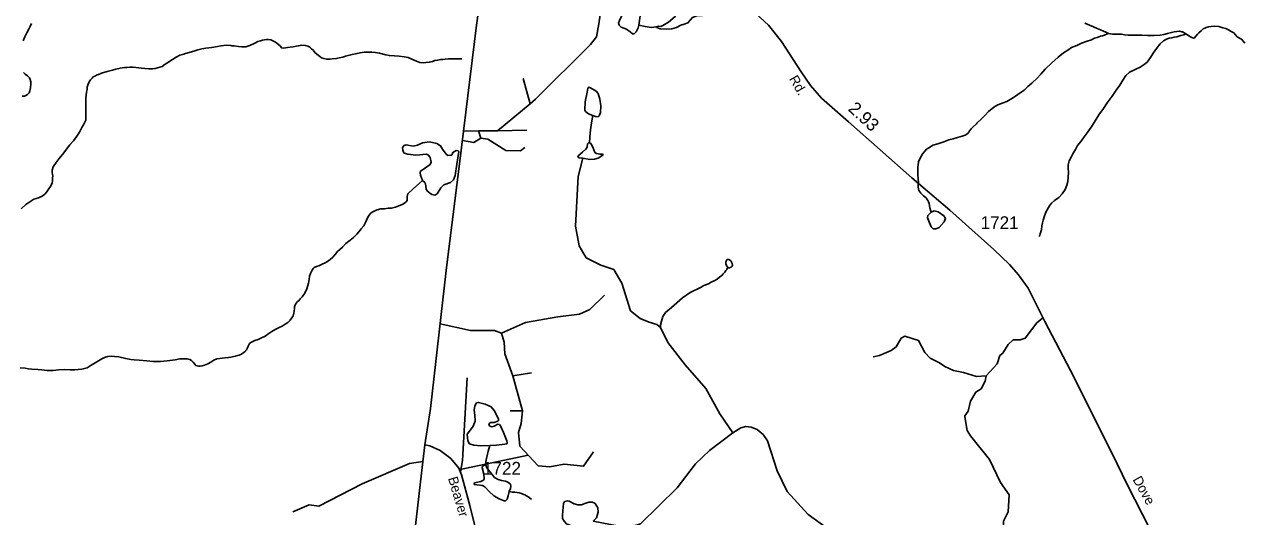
# Model space of a CAD drawing. Extents: x 2056842 to 2160602, y 826753 to 1016856.
# Drawn here: x 2087342 to 2099244, y 851032 to 855845 of the extents above; entities that cross this region are included whole.
import ezdxf

# ---------------------------------------------------------------- set-up
doc = ezdxf.new("R2010")
doc.units = 0
for name, color, linetype in [('Exist Hydrographic Creek Single Shore', 7, 'Continuous'), ('Exist Hydrographic Misc Water Feature', 7, 'Continuous'), ('Exist Road Non-System Type 51', 7, 'Continuous'), ('Exist Road Primary NC Attributed', 7, 'Continuous'), ('Exist Road Secondary Mileage Hundredths English Label', 7, 'Continuous'), ('Exist Road Secondary Type 51 Attributed', 7, 'Continuous'), ('Exist Road Secondary Type 51 Label', 7, 'Continuous'), ('Exist Road Secondary Type 51 Number Label', 7, 'Continuous')]:
    doc.layers.add(name, color=color, linetype=linetype)

msp = doc.modelspace()

# ---------------------------------------------------------------- linework, layer by layer
at = {"layer": 'Exist Hydrographic Creek Single Shore'}
for points in [[(2087412, 855852), (2087397, 855824), (2087386, 855797), (2087366, 855761), (2087346, 855722), (2087330, 855685)], [(2097702, 855856), (2097748, 855836), (2097788, 855820), (2097824, 855804), (2097854, 855792), (2097884, 855778), (2097906, 855768), (2097934, 855756)], [(2097934, 855756), (2097954, 855751), (2097973, 855749), (2097994, 855749), (2098026, 855749), (2098062, 855747), (2098091, 855741), (2098127, 855739), (2098164, 855739), (2098215, 855739), (2098260, 855739), (2098314, 855737), (2098380, 855736), (2098439, 855740), (2098474, 855746), (2098510, 855754), (2098548, 855764), (2098576, 855772), (2098600, 855776), (2098626, 855779), (2098650, 855773), (2098658, 855770), (2098680, 855759), (2098688, 855753)], [(2098688, 855753), (2098704, 855741), (2098728, 855727), (2098748, 855715), (2098764, 855709), (2098770, 855711), (2098790, 855731), (2098802, 855747), (2098816, 855761), (2098842, 855785), (2098858, 855801), (2098874, 855807), (2098888, 855813), (2098912, 855819), (2098936, 855823), (2098972, 855826), (2099012, 855822), (2099052, 855812), (2099080, 855804), (2099106, 855792), (2099132, 855776), (2099158, 855760), (2099176, 855742), (2099192, 855724), (2099214, 855710), (2099233, 855700), (2099266, 855660)], [(2091616, 855507), (2091540, 855509), (2091484, 855506), (2091452, 855504), (2091430, 855502), (2091406, 855500), (2091380, 855496), (2091352, 855490), (2091330, 855482), (2091298, 855474), (2091264, 855470), (2091246, 855469), (2091206, 855472), (2091172, 855483), (2091126, 855505), (2091092, 855519), (2091052, 855527), (2091004, 855535), (2090958, 855537), (2090908, 855540), (2090872, 855548), (2090812, 855562), (2090774, 855568), (2090736, 855572), (2090698, 855574), (2090662, 855572), (2090622, 855567), (2090592, 855561), (2090546, 855551), (2090478, 855533), (2090452, 855525), (2090416, 855517), (2090390, 855511), (2090348, 855507), (2090328, 855505), (2090300, 855505), (2090296, 855504), (2090269, 855511), (2090246, 855518), (2090228, 855529), (2090198, 855552), (2090180, 855570), (2090166, 855588), (2090148, 855606), (2090132, 855620), (2090110, 855632), (2090086, 855638), (2090054, 855640), (2090020, 855636), (2089998, 855632), (2089968, 855626), (2089912, 855617), (2089874, 855611), (2089854, 855615), (2089840, 855633), (2089812, 855657), (2089794, 855671), (2089770, 855685), (2089750, 855693), (2089724, 855697), (2089706, 855696), (2089668, 855690), (2089648, 855683), (2089624, 855676), (2089592, 855660), (2089544, 855638), (2089504, 855624), (2089468, 855624), (2089434, 855628), (2089392, 855634), (2089368, 855636), (2089360, 855638), (2089312, 855641), (2089264, 855635), (2089228, 855627), (2089172, 855617), (2089116, 855613), (2089076, 855605), (2089036, 855595), (2089008, 855586), (2088905, 855556), (2088899, 855554), (2088862, 855542), (2088824, 855524), (2088788, 855500), (2088764, 855484), (2088749, 855476), (2088719, 855454), (2088689, 855434), (2088643, 855419), (2088619, 855413), (2088595, 855409), (2088559, 855409), (2088519, 855413), (2088485, 855417), (2088459, 855421), (2088431, 855423), (2088405, 855425), (2088371, 855425), (2088343, 855424)], [(2088343, 855424), (2088319, 855422), (2088277, 855416), (2088235, 855406), (2088203, 855396), (2088151, 855382), (2088097, 855366), (2088065, 855354), (2088053, 855350), (2088031, 855339), (2088015, 855330), (2088003, 855320), (2087989, 855303), (2087975, 855281), (2087964, 855259), (2087957, 855231), (2087954, 855207), (2087949, 855183), (2087944, 855125), (2087944, 855058), (2087942, 855001), (2087944, 854949), (2087943, 854907), (2087920, 854863), (2087904, 854837), (2087881, 854791), (2087853, 854751), (2087821, 854707), (2087787, 854667), (2087755, 854625), (2087728, 854587), (2087683, 854533), (2087654, 854495), (2087624, 854450), (2087612, 854418), (2087612, 854397), (2087618, 854377), (2087620, 854364), (2087618, 854342), (2087616, 854316), (2087612, 854294), (2087604, 854274), (2087597, 854260), (2087571, 854222), (2087561, 854208), (2087541, 854184), (2087515, 854166), (2087479, 854150), (2087435, 854134), (2087357, 854082), (2087310, 854040)], [(2087333, 855375), (2087351, 855358), (2087371, 855342), (2087383, 855332), (2087391, 855321), (2087399, 855304), (2087404, 855283), (2087404, 855262), (2087402, 855225), (2087400, 855209), (2087396, 855195), (2087388, 855174), (2087380, 855165), (2087372, 855158), (2087356, 855150), (2087342, 855144), (2087320, 855141)], [(2094263, 851851), (2094137, 852038), (2094000, 852285), (2093798, 852515), (2093629, 852735), (2093558, 852881), (2093520, 852910), (2093446, 852933), (2093359, 852969), (2093264, 853045), (2093180, 853313), (2093100, 853449), (2092973, 853489), (2092829, 853563), (2092762, 853679), (2092728, 853870), (2092751, 854357), (2092797, 854537)], [(2091233, 854318), (2091140, 854236), (2091090, 854191), (2091084, 854177), (2091082, 854159), (2091083, 854139), (2091083, 854129), (2091083, 854121), (2091072, 854109), (2091056, 854097), (2091039, 854087), (2091027, 854081), (2091001, 854069), (2090969, 854057), (2090929, 854049), (2090897, 854047), (2090861, 854042), (2090825, 854040), (2090789, 854030), (2090767, 854022), (2090741, 854010), (2090727, 854000), (2090711, 853978), (2090699, 853960), (2090685, 853930), (2090671, 853902), (2090658, 853876), (2090634, 853844), (2090611, 853816), (2090590, 853793), (2090558, 853762), (2090526, 853735), (2090484, 853701), (2090450, 853667), (2090402, 853623), (2090380, 853595), (2090354, 853569), (2090328, 853547), (2090302, 853527), (2090280, 853513), (2090250, 853499), (2090218, 853485), (2090195, 853476), (2090173, 853468), (2090163, 853459), (2090153, 853441), (2090139, 853410), (2090127, 853382), (2090123, 853350), (2090117, 853314), (2090101, 853258), (2090082, 853216), (2090055, 853180), (2090038, 853160), (2090024, 853142), (2090010, 853134), (2090000, 853122), (2089990, 853110), (2089984, 853094), (2089982, 853084), (2089980, 853066), (2089978, 853042), (2089976, 853020), (2089968, 852996), (2089954, 852974), (2089938, 852952), (2089916, 852930), (2089890, 852912), (2089859, 852894), (2089830, 852880), (2089799, 852865), (2089761, 852841), (2089729, 852821), (2089693, 852795), (2089659, 852779), (2089625, 852765), (2089595, 852753), (2089555, 852735), (2089541, 852723), (2089529, 852700), (2089521, 852681), (2089511, 852663), (2089503, 852654), (2089501, 852650), (2089487, 852637), (2089468, 852623), (2089458, 852618), (2089441, 852612), (2089403, 852600), (2089358, 852590), (2089337, 852588), (2089273, 852582), (2089227, 852576), (2089223, 852576), (2089193, 852561), (2089165, 852543), (2089135, 852527)], [(2089135, 852527), (2089103, 852513), (2089079, 852507), (2089060, 852503), (2089044, 852503), (2089018, 852511), (2089008, 852523), (2088992, 852541), (2088975, 852559), (2088959, 852567), (2088932, 852575), (2088902, 852575), (2088860, 852573), (2088816, 852566), (2088736, 852554), (2088671, 852550), (2088596, 852550), (2088540, 852555), (2088464, 852563), (2088415, 852565), (2088383, 852569), (2088332, 852577), (2088265, 852593), (2088221, 852598), (2088194, 852600), (2088158, 852596), (2088125, 852588), (2088099, 852576), (2088034, 852536), (2087996, 852514), (2087954, 852488), (2087902, 852474), (2087832, 852467), (2087790, 852467), (2087736, 852469), (2087674, 852467), (2087622, 852462), (2087566, 852460), (2087514, 852466), (2087474, 852470), (2087414, 852474), (2087378, 852478), (2087350, 852482), (2087302, 852486)], [(2092899, 850988), (2093237, 850923), (2093362, 850963), (2093719, 851314), (2093899, 851549), (2094035, 851680), (2094263, 851851)], [(2095654, 849692), (2095635, 849828), (2095664, 850105), (2095654, 850159), (2095558, 850361), (2095410, 850616), (2095292, 850772), (2095198, 850908), (2094999, 851052), (2094793, 851278), (2094695, 851479), (2094601, 851772), (2094560, 851834), (2094500, 851884), (2094441, 851908), (2094392, 851913), (2094341, 851900), (2094263, 851851)]]:
    msp.add_lwpolyline(points, dxfattribs=at)
at = {"layer": 'Exist Hydrographic Misc Water Feature'}
for points in [[(2093515, 855819), (2093536, 855826), (2093561, 855824), (2093581, 855834), (2093634, 855867), (2093700, 855922), (2093729, 855955), (2093731, 855973), (2093724, 855993), (2093679, 856082), (2093679, 856097), (2093686, 856102), (2093702, 856092), (2093743, 856054), (2093770, 856045), (2093781, 856052), (2093828, 856094), (2093861, 856132), (2093880, 856136), (2093898, 856128), (2093917, 856098), (2093928, 856061)], [(2093344, 855838), (2093360, 855951), (2093369, 856056), (2093358, 856088), (2093329, 856104), (2093284, 856112), (2093256, 856106), (2093236, 856065), (2093199, 855973), (2093156, 855881), (2093148, 855855), (2093152, 855836), (2093174, 855818), (2093225, 855799), (2093262, 855770), (2093282, 855751), (2093299, 855752), (2093319, 855772), (2093339, 855812), (2093344, 855838)], [(2093928, 856061), (2093964, 855985), (2093976, 855948), (2093975, 855937), (2093966, 855932), (2093946, 855931), (2093912, 855928), (2093869, 855910), (2093846, 855886), (2093824, 855860), (2093788, 855846), (2093757, 855837), (2093714, 855814), (2093667, 855800), (2093615, 855796), (2093553, 855802), (2093522, 855814), (2093515, 855819)], [(2093344, 855838), (2093408, 855822), (2093466, 855815), (2093515, 855819)], [(2096200, 854007), (2096188, 854051), (2096184, 854075), (2096180, 854093), (2096175, 854111), (2096170, 854123), (2096154, 854143), (2096151, 854147), (2096127, 854169), (2096101, 854195), (2096080, 854221), (2096073, 854253), (2096075, 854271), (2096077, 854303), (2096075, 854331), (2096071, 854377), (2096071, 854445), (2096079, 854499), (2096096, 854543), (2096120, 854581), (2096142, 854609), (2096156, 854623), (2096186, 854641), (2096218, 854663), (2096266, 854677), (2096324, 854696), (2096374, 854716), (2096416, 854726), (2096460, 854738), (2096505, 854750), (2096532, 854760), (2096560, 854778), (2096568, 854792), (2096577, 854804), (2096592, 854822), (2096613, 854844), (2096643, 854872), (2096647, 854877), (2096693, 854922), (2096725, 854955), (2096761, 854991), (2096815, 855035), (2096852, 855057), (2096905, 855077), (2096941, 855091), (2097006, 855129), (2097048, 855158), (2097110, 855202), (2097146, 855236), (2097184, 855270), (2097237, 855320), (2097274, 855358), (2097316, 855406), (2097380, 855469), (2097441, 855523), (2097493, 855565), (2097535, 855593), (2097573, 855619), (2097623, 855639), (2097669, 855659), (2097726, 855680), (2097769, 855694), (2097798, 855708), (2097824, 855716), (2097856, 855728), (2097876, 855732), (2097893, 855740), (2097914, 855750), (2097934, 855756)], [(2097257, 853772), (2097262, 853784), (2097266, 853798), (2097272, 853817), (2097278, 853836), (2097282, 853874), (2097288, 853905), (2097296, 853931), (2097308, 853971), (2097326, 854015), (2097357, 854069), (2097377, 854095), (2097405, 854121), (2097448, 854153), (2097481, 854189), (2097509, 854231), (2097525, 854271), (2097535, 854307), (2097541, 854351), (2097543, 854401), (2097540, 854439), (2097540, 854471), (2097548, 854509), (2097568, 854545), (2097590, 854585), (2097610, 854622), (2097631, 854660), (2097666, 854704), (2097695, 854744), (2097735, 854796), (2097777, 854860), (2097805, 854902), (2097839, 854960), (2097885, 855022), (2097920, 855078), (2097968, 855141), (2098010, 855201), (2098044, 855251), (2098074, 855299), (2098103, 855343), (2098135, 855373), (2098153, 855385), (2098176, 855395), (2098201, 855407), (2098243, 855425), (2098283, 855452), (2098313, 855475), (2098345, 855522), (2098371, 855562), (2098401, 855608), (2098437, 855654), (2098470, 855684), (2098500, 855700), (2098525, 855710), (2098552, 855714), (2098576, 855720), (2098600, 855724), (2098640, 855735), (2098670, 855743), (2098688, 855753)], [(2092897, 854952), (2092855, 854971), (2092826, 854990), (2092819, 855006), (2092820, 855087), (2092839, 855182), (2092848, 855220), (2092860, 855229), (2092874, 855225), (2092927, 855192), (2092948, 855169), (2092963, 855114), (2092973, 855049), (2092970, 854983), (2092959, 854950), (2092948, 854941), (2092921, 854943), (2092897, 854952)], [(2092897, 854952), (2092884, 854882), (2092873, 854813), (2092867, 854741), (2092863, 854687)], [(2091233, 854318), (2091258, 854294), (2091265, 854267), (2091269, 854230), (2091288, 854207), (2091324, 854181), (2091353, 854176), (2091375, 854189), (2091410, 854247), (2091440, 854277), (2091506, 854300), (2091535, 854323), (2091551, 854367), (2091568, 854478), (2091586, 854600), (2091580, 854608), (2091562, 854611), (2091528, 854592), (2091520, 854571), (2091511, 854567), (2091478, 854563), (2091464, 854574), (2091427, 854623), (2091408, 854657), (2091373, 854679), (2091300, 854695), (2091230, 854686), (2091182, 854663), (2091141, 854655), (2091071, 854666), (2091051, 854661), (2091037, 854640), (2091039, 854615), (2091046, 854594), (2091054, 854584), (2091087, 854575), (2091167, 854566), (2091271, 854575), (2091291, 854566), (2091307, 854542), (2091315, 854497), (2091306, 854475), (2091250, 854434), (2091212, 854410), (2091208, 854394), (2091211, 854369), (2091233, 854318)], [(2092863, 854687), (2092853, 854685), (2092845, 854676), (2092839, 854645), (2092827, 854624), (2092796, 854595), (2092753, 854559), (2092750, 854550), (2092762, 854540), (2092797, 854537)], [(2092797, 854537), (2092865, 854524), (2092911, 854525), (2092949, 854536), (2092995, 854566), (2092996, 854571), (2092988, 854576), (2092965, 854577), (2092930, 854581), (2092916, 854593), (2092895, 854645), (2092879, 854674), (2092872, 854683), (2092863, 854687)], [(2096200, 854007), (2096169, 853975), (2096164, 853955), (2096177, 853920), (2096200, 853866), (2096221, 853846), (2096248, 853845), (2096278, 853859), (2096329, 853915), (2096340, 853945), (2096326, 853973), (2096271, 854012), (2096230, 854020), (2096216, 854015), (2096200, 854007)], [(2094214, 853469), (2094220, 853465), (2094232, 853463), (2094248, 853471), (2094258, 853481), (2094260, 853489), (2094258, 853507), (2094252, 853521), (2094250, 853525), (2094244, 853533), (2094232, 853541), (2094224, 853545), (2094218, 853547), (2094212, 853547), (2094206, 853543), (2094202, 853537), (2094195, 853523), (2094194, 853513), (2094196, 853503), (2094202, 853487), (2094210, 853473), (2094214, 853469)], [(2094214, 853469), (2094212, 853463), (2094204, 853449), (2094196, 853437), (2094184, 853421), (2094170, 853405), (2094152, 853387), (2094138, 853375), (2094112, 853355), (2094088, 853339), (2094053, 853323), (2094026, 853309), (2093980, 853291), (2093953, 853274), (2093847, 853223), (2093771, 853171), (2093664, 853078), (2093606, 853026), (2093579, 852988), (2093560, 852919), (2093560, 852915), (2093558, 852905), (2093558, 852897), (2093558, 852889), (2093558, 852881)], [(2091891, 851727), (2091801, 851725), (2091732, 851729), (2091691, 851742), (2091673, 851773), (2091669, 851838), (2091681, 851855), (2091728, 851915), (2091745, 851964), (2091743, 852025), (2091736, 852074), (2091744, 852115), (2091760, 852144), (2091778, 852148), (2091843, 852130), (2091902, 852104), (2091932, 852070), (2091974, 851989), (2091975, 851972), (2091966, 851964), (2091931, 851953), (2091899, 851953), (2091887, 851945), (2091881, 851933), (2091891, 851917), (2091908, 851910), (2091933, 851917), (2091966, 851937), (2091983, 851934), (2091993, 851920), (2092024, 851854), (2092054, 851774), (2092059, 851754), (2092054, 851745), (2092035, 851740), (2091955, 851730), (2091891, 851727)], [(2091850, 851534), (2091850, 851546), (2091850, 851570), (2091873, 851673), (2091891, 851727)], [(2091850, 851534), (2091835, 851534), (2091818, 851525), (2091816, 851509), (2091831, 851447), (2091834, 851403), (2091826, 851387), (2091802, 851376), (2091741, 851362), (2091735, 851353), (2091739, 851346), (2091762, 851344), (2091818, 851337), (2091842, 851324), (2091882, 851278), (2091927, 851235), (2091980, 851206), (2092028, 851185), (2092043, 851187), (2092059, 851203), (2092069, 851235), (2092079, 851277)], [(2092079, 851277), (2092090, 851307), (2092096, 851329), (2092091, 851348), (2092065, 851370), (2092042, 851380), (2092004, 851386), (2091971, 851394), (2091935, 851415), (2091897, 851462), (2091860, 851509), (2091850, 851534)], [(2092295, 851201), (2092271, 851223), (2092249, 851235), (2092231, 851245), (2092213, 851253), (2092199, 851259), (2092177, 851265), (2092155, 851269), (2092135, 851271), (2092115, 851271), (2092107, 851271), (2092093, 851273), (2092079, 851277)], [(2092685, 850943), (2092640, 850963), (2092616, 850988), (2092600, 851015), (2092599, 851047), (2092609, 851164), (2092621, 851179), (2092647, 851188), (2092665, 851183), (2092712, 851156), (2092749, 851148), (2092785, 851148), (2092818, 851161), (2092857, 851174), (2092894, 851172), (2092917, 851160), (2092946, 851117), (2092949, 851077), (2092930, 851019), (2092899, 850988)]]:
    msp.add_lwpolyline(points, dxfattribs=at)
at = {"layer": 'Exist Road Non-System Type 51'}
for p, q in [((2092283, 855069), (2092215, 855316)), ((2092283, 855069), (2091964, 854805)), ((2091778, 854802), (2091633, 854800)), ((2091964, 854805), (2091778, 854802)), ((2091778, 854802), (2091803, 854731)), ((2091964, 854805), (2092251, 854810)), ((2092114, 852407), (2092297, 852437)), ((2092114, 852407), (2092210, 852067)), ((2092210, 852067), (2092089, 852067)), ((2091598, 851492), (2092264, 851633))]:
    msp.add_line(p, q, dxfattribs=at)
for points in [[(2092987, 856068), (2092953, 855849), (2092933, 855721), (2092872, 855648), (2092337, 855113), (2092283, 855069)], [(2091803, 854731), (2091734, 854690), (2091622, 854710)], [(2091803, 854731), (2091869, 854723), (2092046, 854611), (2092189, 854609), (2092231, 854640)], [(2092002, 852827), (2092239, 852931), (2092555, 852985), (2092766, 853010), (2092866, 853056), (2093011, 853197)], [(2091404, 852918), (2091699, 852852), (2091936, 852852), (2092002, 852827)], [(2097292, 852977), (2097232, 852926), (2097120, 852776), (2097070, 852760), (2097003, 852760), (2096954, 852714), (2096900, 852631), (2096871, 852606), (2096846, 852527), (2096738, 852410)], [(2092002, 852827), (2092031, 852736), (2092035, 852624), (2092114, 852407)], [(2096738, 852410), (2096645, 852403), (2096516, 852441), (2096419, 852461), (2096336, 852499), (2096282, 852536), (2096192, 852580), (2096138, 852638), (2096078, 852754), (2095945, 852796), (2095908, 852777), (2095858, 852692), (2095810, 852657), (2095696, 852607), (2095636, 852594)], [(2091604, 851470), (2091622, 851582), (2091668, 852389)], [(2096738, 852410), (2096728, 852355), (2096689, 852280), (2096639, 852249), (2096585, 852162), (2096562, 852064), (2096529, 852017), (2096531, 852008), (2096552, 851875), (2096585, 851823), (2096771, 851591), (2096877, 851367), (2096964, 851246), (2096954, 851078), (2096909, 850988), (2096901, 850836), (2096894, 850761), (2096805, 850645)], [(2092210, 852067), (2092197, 851942), (2092168, 851855), (2092181, 851722), (2092361, 851528), (2092474, 851520), (2092615, 851545), (2092806, 851524), (2092901, 851665)], [(2091236, 851572), (2091104, 851550), (2090641, 851351), (2090218, 851135), (2090124, 851146), (2089965, 851079)]]:
    msp.add_lwpolyline(points, dxfattribs=at)
at = {"layer": 'Exist Road Primary NC Attributed'}
for points in [[(2091255, 851735), (2091311, 852089), (2091463, 853439), (2091614, 854639), (2091758, 855836), (2091802, 856137), (2091911, 857005), (2091950, 857348), (2092045, 858101), (2092082, 858431), (2092171, 859143), (2092214, 859513), (2092249, 859810)], [(2090794, 848077), (2090830, 848397), (2090890, 848807), (2090995, 849693), (2091022, 849930), (2091164, 850945), (2091222, 851456), (2091255, 851735)]]:
    msp.add_lwpolyline(points, dxfattribs=at)
at = {"layer": 'Exist Road Secondary Type 51 Attributed'}
for points in [[(2094489, 855952), (2094613, 855835), (2094738, 855677), (2094930, 855379), (2095021, 855248), (2095131, 855123), (2095393, 854891), (2096013, 854345), (2096383, 854027), (2096812, 853642), (2096967, 853498), (2097055, 853396), (2097148, 853265), (2097311, 852940), (2097562, 852460), (2097966, 851655), (2098118, 851341), (2098630, 850340)], [(2091255, 851735), (2091303, 851723), (2091405, 851679), (2091507, 851600), (2091586, 851505), (2091612, 851441), (2091693, 851142), (2091786, 850768), (2091811, 850668), (2091816, 850540), (2091815, 850368), (2091823, 850187), (2091830, 850008)]]:
    msp.add_lwpolyline(points, dxfattribs=at)

# ---------------------------------------------------------------- texts
at = {"layer": 'Exist Road Secondary Mileage Hundredths English Label'}
msp.add_text('2.93', height=125, rotation=317.1775, dxfattribs=at).set_placement((2095382, 855009))
at = {"layer": 'Exist Road Secondary Type 51 Label'}
for s, rotation, p in [('Rd.', 300.1275, (2094810, 855312)), ('Beaver', 286.5778, (2091480, 851407)), ('Dove', 299.0558, (2098167, 851395))]:
    msp.add_text(s, height=95, rotation=rotation, dxfattribs=at).set_placement(p)
at = {"layer": 'Exist Road Secondary Type 51 Number Label'}
for s, p in [('1721', (2096684, 853843)), ('1722', (2091822, 851442))]:
    msp.add_text(s, height=125, dxfattribs=at).set_placement(p)

doc.saveas('drawing.dxf')
